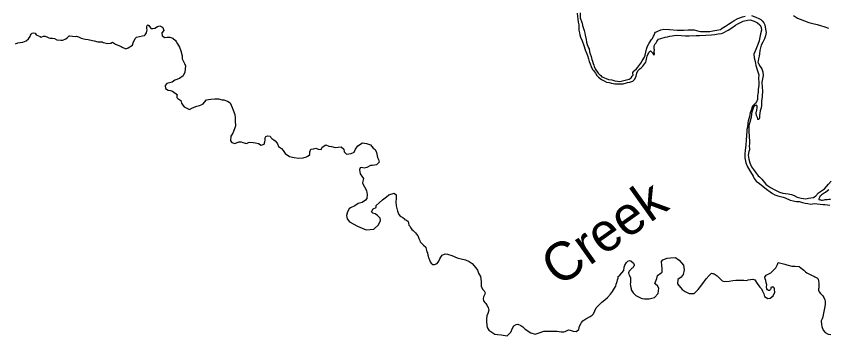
# Model space of a CAD drawing. Extents: x 79818 to 83933, y 50884 to 53307.
# Drawn here: x 81014.4 to 81163.3, y 52935.5 to 52994.1 of the extents above; entities that cross this region are included whole.
import ezdxf

# ---------------------------------------------------------------- set-up
doc = ezdxf.new("R2010")
doc.units = 0
for name, color, linetype in [('Level 10', 7, 'Continuous'), ('Level 2', 7, 'Continuous'), ('Level 9', 7, 'Continuous')]:
    doc.layers.add(name, color=color, linetype=linetype)

msp = doc.modelspace()

# ---------------------------------------------------------------- linework, layer by layer
at = {"layer": 'Level 10'}
msp.add_lwpolyline([(81156.86, 52994.25), (81157.61, 52993.8), (81158.1, 52993.59), (81158.86, 52993.27), (81159.65, 52993), (81160.42, 52992.79), (81161.19, 52992.6), (81161.8, 52992.44), (81162.57, 52992.17), (81163.25, 52991.91)], dxfattribs=at)
at = {"layer": 'Level 2'}
for points in [[(81028.39, 52989.68), (81028.7, 52989.64), (81029.37, 52989.42), (81030.14, 52989.44), (81030.35, 52989.32), (81030.66, 52989.24), (81031.14, 52989.11), (81031.71, 52989.18), (81032.05, 52989.34), (81032.62, 52989.02), (81033.64, 52988.55), (81033.82, 52988.43), (81034.49, 52988.17), (81034.94, 52988.33), (81035.69, 52988.8), (81035.81, 52989.27), (81036.19, 52990.05), (81036.43, 52990.31), (81037.02, 52990.4), (81037.53, 52990.51), (81037.91, 52990.59), (81038.05, 52990.71), (81038.27, 52991.09), (81038.36, 52991.37), (81038.38, 52991.64), (81038.36, 52991.85), (81038.36, 52992.2), (81038.37, 52992.42), (81038.49, 52992.53), (81038.72, 52992.41), (81039, 52992), (81039.18, 52991.86), (81039.44, 52991.85), (81039.78, 52991.91), (81040.26, 52992.24), (81040.71, 52992.36), (81041.07, 52992.19), (81041.27, 52992.04), (81041.47, 52991.52), (81041.1, 52991.09), (81041.15, 52990.51), (81041.62, 52990.24), (81042.05, 52990.29), (81042.58, 52990.3), (81043.1, 52990.1), (81043.56, 52989.7), (81043.73, 52989.47), (81043.93, 52989.08), (81044.33, 52988.47), (81044.57, 52987.79), (81044.8, 52986.84), (81044.84, 52986.33), (81045.26, 52985.47), (81045.42, 52985.02), (81045.32, 52983.89), (81045.01, 52983.19), (81044.32, 52982.68), (81043.45, 52982.38), (81042.95, 52982.01), (81042.51, 52981.89), (81042.01, 52981.8), (81041.71, 52981.41), (81041.74, 52980.84), (81042.22, 52980.57), (81042.67, 52980.49), (81043.03, 52980.38), (81043.94, 52979.72), (81043.85, 52979.57), (81043.85, 52979.22), (81043.99, 52979.01), (81044.57, 52978.66), (81044.68, 52978.17), (81044.96, 52977.8), (81045.16, 52977.53), (81046.17, 52977.01), (81046.71, 52977.32), (81047.52, 52977.63), (81047.99, 52977.74), (81048.61, 52977.97), (81049.24, 52978.81), (81049.66, 52978.84), (81050.05, 52978.92), (81050.77, 52978.96), (81051.45, 52978.97), (81052.14, 52978.76), (81052.42, 52978.79), (81053.13, 52978.52), (81053.63, 52978.26), (81053.97, 52977.4), (81054.16, 52976.86), (81054.46, 52976.09), (81054.5, 52975.51), (81054.53, 52974.99), (81054.57, 52973.98), (81054.12, 52972.65), (81053.73, 52972.1), (81053.68, 52971.28), (81053.9, 52970.94), (81054.48, 52970.76), (81055.19, 52971.06), (81055.63, 52971.09)], [(81014.29, 52989.06), (81014.68, 52989.22), (81015.11, 52989.33), (81015.6, 52989.39), (81016.24, 52989.6), (81016.65, 52990), (81016.95, 52990.41), (81017.01, 52990.63), (81017.14, 52990.84), (81017.3, 52990.99), (81017.62, 52991.07), (81017.86, 52991), (81018.08, 52990.72), (81018.2, 52990.67), (81018.49, 52990.5), (81018.77, 52990.39), (81018.95, 52990.31), (81019.09, 52990.35), (81019.41, 52990.47), (81019.68, 52990.48), (81020.16, 52990.27), (81020.37, 52990.15), (81020.64, 52990.09), (81021.03, 52990.09), (81021.44, 52990.02), (81021.83, 52989.82), (81022.55, 52989.72), (81022.92, 52989.76), (81023.5, 52989.96), (81023.79, 52990.23), (81024.08, 52990.51), (81024.23, 52990.52), (81024.71, 52990.44), (81025.2, 52990.39), (81025.44, 52990.44), (81025.79, 52990.35), (81026.3, 52990.13), (81027.04, 52989.89), (81027.56, 52989.83), (81028.39, 52989.68)], [(81055.63, 52971.09), (81055.94, 52970.96), (81056.6, 52970.76), (81056.98, 52970.96), (81057.24, 52971.01), (81057.82, 52970.96), (81058.22, 52970.91), (81058.83, 52970.79), (81059.27, 52970.49), (81059.65, 52970.56), (81059.82, 52970.67), (81059.99, 52971.07), (81060, 52971.45), (81060.02, 52971.82), (81060.16, 52972.03), (81060.42, 52972.15), (81060.91, 52972.13), (81061.08, 52971.9), (81061.27, 52971.7), (81061.6, 52971.44), (81061.83, 52971.24), (81062.17, 52970.88), (81062.29, 52970.7), (81062.46, 52970.25), (81063.04, 52969.88), (81063.32, 52969.48), (81063.66, 52968.96), (81064.47, 52968.38), (81065.36, 52968.22), (81066.11, 52968.11), (81067, 52968.13), (81067.57, 52968.31), (81067.87, 52968.42), (81068.23, 52968.75), (81068.23, 52969.23), (81068.42, 52969.71), (81068.9, 52969.82), (81069.33, 52969.89), (81069.74, 52969.74), (81070.28, 52969.7), (81070.45, 52970.11), (81071.17, 52970.51), (81071.68, 52970.3), (81072.2, 52970.23), (81072.85, 52970.06), (81073.38, 52970.11), (81073.94, 52970.15), (81074.45, 52969.74), (81074.49, 52969.22), (81074.91, 52968.83), (81075.35, 52968.9), (81075.78, 52968.94), (81076.31, 52969.17), (81076.59, 52969.72), (81077.03, 52970.36), (81077.84, 52970.87), (81078.6, 52970.8), (81079.33, 52970.55), (81079.83, 52969.94), (81080.2, 52969.65), (81080.4, 52969.15), (81080.62, 52968.22), (81080.77, 52967.82), (81080.89, 52967.36), (81080.41, 52966.83), (81079.71, 52966.71), (81079.3, 52966.71), (81078.64, 52966.38), (81078.18, 52966.25), (81077.65, 52966.37), (81077.45, 52966.29), (81077.32, 52965.91), (81077.44, 52965.22), (81077.83, 52964.6), (81078.05, 52964.34), (81077.93, 52963.86), (81077.84, 52963.47), (81078.24, 52962.79), (81078.62, 52962.15), (81078.69, 52961.41), (81078.65, 52960.68), (81078.38, 52960.38), (81077.77, 52959.92), (81077.06, 52959.75), (81076.45, 52959.35), (81075.65, 52958.95), (81075.42, 52958.78), (81075.11, 52958.23), (81074.92, 52957.56), (81075.02, 52956.97), (81075.5, 52956.38), (81076.95, 52955.63), (81078.23, 52955.08), (81078.62, 52954.9), (81079.94, 52955.06), (81080.81, 52955.82), (81081.17, 52956.62), (81081.07, 52957.08), (81080.63, 52957.58), (81080.18, 52957.86), (81079.77, 52957.97)], [(81079.77, 52957.97), (81079.53, 52958.22), (81079.8, 52958.78), (81080.35, 52959), (81080.37, 52959.39), (81080.94, 52959.9), (81081.54, 52960.41), (81082.26, 52961.01), (81082.71, 52961.37), (81083.65, 52961.63), (81084.04, 52961.33), (81084.04, 52960.65), (81083.94, 52960.08), (81084, 52959.34), (81084.16, 52958.83), (81084.3, 52958.37), (81084.54, 52957.77), (81084.78, 52957.46), (81085.23, 52957.18), (81085.53, 52956.93), (81085.57, 52956.81)], [(81085.57, 52956.81), (81085.95, 52956.69), (81086.2, 52956.43), (81086.28, 52956.16), (81086.37, 52955.81), (81086.53, 52955.59), (81086.75, 52955.17), (81086.91, 52954.98), (81087.14, 52954.81), (81087.59, 52954.4), (81087.96, 52953.92), (81087.99, 52953.88), (81088.2, 52953.36), (81088.35, 52952.95), (81088.45, 52952.71), (81088.67, 52952.5), (81089.04, 52952.11), (81089.44, 52951.72), (81089.55, 52951.4), (81089.68, 52950.91), (81089.76, 52950.74), (81089.81, 52950.26), (81090, 52949.69), (81090.12, 52949.45), (81090.24, 52949.08), (81090.44, 52948.82), (81090.78, 52948.59), (81091.08, 52948.58), (81091.52, 52948.76), (81091.86, 52949.16), (81092.01, 52949.59), (81092.22, 52949.9), (81092.43, 52950.3), (81093.04, 52950.51), (81093.44, 52950.48), (81094.24, 52950.19), (81095.23, 52949.77), (81095.96, 52949.62), (81096.72, 52949.41), (81097.4, 52949.11), (81097.95, 52948.77), (81098.62, 52947.95), (81098.95, 52947.55), (81099.12, 52946.97), (81099.51, 52946.34), (81099.58, 52945.47), (81099.61, 52945.04), (81099.62, 52944.53), (81099.89, 52943.97), (81100.16, 52943.74), (81100.33, 52943.38), (81100.28, 52943.15), (81100.17, 52942.86), (81100.06, 52942.66), (81099.98, 52942.24), (81100.05, 52941.88), (81100.31, 52941.59), (81100.44, 52941.4), (81100.64, 52941.12), (81100.9, 52940.67), (81101.03, 52940.19), (81100.8, 52939.58), (81100.66, 52939.12), (81100.57, 52938.61), (81100.56, 52938.12), (81100.65, 52937.42), (81100.73, 52937.01), (81101.01, 52936.54), (81101.54, 52936.15), (81102.14, 52935.81), (81102.63, 52935.71), (81103.3, 52935.67), (81104.36, 52935.49), (81105.06, 52936.18), (81105.37, 52936.88), (81105.62, 52937.3), (81106, 52937.57), (81106.32, 52937.6), (81106.87, 52937.39), (81107.24, 52937.12), (81107.68, 52936.72), (81108.74, 52936.02), (81109.49, 52935.81), (81110.23, 52936.06), (81111.11, 52936.33), (81111.91, 52936.36), (81112.58, 52936.33), (81113.19, 52936.32), (81113.55, 52936.34), (81114.24, 52936.24), (81114.48, 52936.19), (81114.74, 52936.24), (81115.01, 52936.28), (81115.61, 52936.57), (81115.93, 52936.52), (81116.48, 52936.33), (81117.03, 52936.3), (81117.48, 52936.64), (81117.66, 52937.24), (81117.87, 52937.67), (81118.01, 52937.91)], [(81118.01, 52937.91), (81118.24, 52938.25), (81118.4, 52938.35), (81118.78, 52938.59), (81119.58, 52939.01), (81119.93, 52939.25), (81120.18, 52939.53), (81120.43, 52940.07), (81120.69, 52940.6), (81121.29, 52941.21), (81121.73, 52941.63), (81122.3, 52942.09), (81122.76, 52942.49), (81123.32, 52943.14), (81123.68, 52943.62), (81124.05, 52944.21), (81124.26, 52944.61), (81124.36, 52944.93), (81124.56, 52945.44), (81124.58, 52945.75), (81124.69, 52946.08), (81124.73, 52946.36), (81125, 52946.59), (81125.39, 52947.01), (81125.73, 52947.48), (81125.83, 52948.1), (81125.96, 52948.47), (81126.22, 52948.94), (81126.22, 52948.95), (81126.49, 52949.19), (81126.81, 52949.31), (81127.06, 52949.24), (81127.53, 52948.81), (81127.6, 52948.66), (81127.62, 52948.56), (81127.63, 52948.35), (81127.53, 52948.19), (81127.38, 52947.98), (81127.19, 52947.84), (81127.07, 52947.73), (81126.76, 52947.37), (81126.7, 52947.2), (81126.64, 52947.02), (81126.69, 52946.79), (81126.81, 52946.58), (81126.98, 52946.14), (81127, 52945.71), (81126.99, 52945.63), (81126.99, 52945.15), (81126.94, 52945), (81126.98, 52944.66), (81127.01, 52944.36), (81127.09, 52944.17), (81127.12, 52943.89), (81127.45, 52943.38), (81127.97, 52942.91), (81128.21, 52942.75), (81128.35, 52942.68), (81128.94, 52942.37), (81129.14, 52942.3), (81129.53, 52942.27), (81129.72, 52942.26), (81130.37, 52942.29), (81131.39, 52942.5), (81132.04, 52943.27), (81132.16, 52944.24), (81131.93, 52944.64), (81131.58, 52944.95), (81131.43, 52945.08), (81131.69, 52945.7), (81131.83, 52945.99), (81131.91, 52946.57), (81132.62, 52947.05), (81132.8, 52947.19), (81132.75, 52947.85), (81132.72, 52948.36), (81132.68, 52949.09), (81132.89, 52949.43), (81133.68, 52949.76), (81134.28, 52949.79), (81135.21, 52949.84), (81135.88, 52949.34), (81136.67, 52948.44), (81136.83, 52947.57), (81136.62, 52946.76), (81136.27, 52946.26), (81135.66, 52945.79), (81135.59, 52945.02), (81136.44, 52944), (81136.98, 52943.6), (81137.72, 52943.26), (81138.65, 52943.27), (81139.4, 52943.97), (81140.08, 52944.84), (81140.83, 52945.93), (81141.38, 52946.56), (81141.85, 52946.95), (81142, 52946.93), (81142.12, 52946.94), (81142.34, 52946.88), (81142.89, 52946.5)], [(81142.89, 52946.5), (81143.32, 52946), (81143.8, 52945.6), (81144.25, 52945.42), (81145.08, 52945.5), (81145.72, 52945.61), (81146.26, 52945.71), (81146.79, 52945.72), (81147.14, 52945.7), (81147.74, 52945.67), (81148.25, 52945.64), (81148.57, 52945.73), (81148.94, 52945.84), (81149.42, 52945.88), (81149.78, 52945.78), (81150.17, 52945.07), (81150.47, 52944.65), (81150.71, 52944.41), (81151, 52944.08), (81151.19, 52943.67), (81151.4, 52943.16), (81151.54, 52942.71), (81152.17, 52942.3), (81152.55, 52942.37), (81153.13, 52942.85), (81153.43, 52943.49), (81153.39, 52943.97), (81153.38, 52944.1), (81153.33, 52944.31), (81153.16, 52944.41), (81153.09, 52944.44), (81152.92, 52944.47), (81152.85, 52944.44), (81152.69, 52944.35), (81152.67, 52944.13), (81152.66, 52944), (81152.54, 52943.83), (81152.44, 52943.79), (81152.43, 52943.79), (81152.28, 52943.78), (81152.26, 52943.8), (81152.07, 52943.95), (81151.96, 52944.13), (81151.9, 52944.45), (81151.94, 52944.82), (81151.85, 52945.2), (81151.77, 52945.61), (81151.68, 52945.92), (81151.6, 52946.24), (81151.82, 52946.64), (81152.69, 52947.07), (81153.22, 52947.56), (81153.62, 52947.93), (81153.93, 52948.56), (81154.03, 52948.92), (81155.28, 52948.6), (81155.6, 52948.52), (81156.56, 52948.25), (81157.15, 52948.26), (81157.91, 52948.23), (81158.22, 52947.93), (81158.48, 52947.71), (81158.73, 52947.5), (81159.04, 52947.22), (81159.28, 52947.05), (81159.65, 52946.83), (81159.88, 52946.71), (81160.28, 52946.55), (81160.58, 52946.41), (81160.78, 52946.3), (81161.24, 52946.07), (81161.28, 52945.97), (81161.38, 52945.8), (81161.42, 52945.68), (81161.45, 52945.48), (81161.5, 52945.19), (81161.5, 52944.91), (81161.49, 52944.29), (81161.46, 52944.13), (81161.46, 52943.85), (81161.55, 52943.58), (81161.77, 52943.26), (81162.02, 52943), (81162.2, 52942.8), (81162.43, 52942.49), (81162.57, 52942.06), (81162.64, 52941.86), (81162.66, 52941.32), (81162.59, 52940.89), (81162.5, 52940.27), (81162.34, 52939.62), (81162.23, 52938.99), (81162.08, 52938.57), (81161.95, 52938.24), (81162, 52937.57), (81162.02, 52937.18), (81162.3, 52936.51), (81162.68, 52936.12), (81163.23, 52935.8), (81163.71, 52935.7)]]:
    msp.add_lwpolyline(points, dxfattribs=at)
at = {"layer": 'Level 9'}
for points in [[(81117.21, 52994.68), (81117.28, 52994.08), (81117.34, 52993.59), (81117.4, 52993.04), (81117.48, 52992.56), (81117.53, 52992.07), (81117.53, 52991.57), (81117.63, 52991.1), (81117.71, 52990.7), (81117.81, 52990.3), (81118.09, 52989.58), (81118.42, 52988.77), (81118.65, 52987.93), (81118.98, 52987.24), (81119.11, 52986.92), (81119.28, 52986.33), (81119.4, 52985.82), (81119.6, 52985.37), (81119.74, 52984.88), (81120.01, 52984.37), (81120.18, 52984.17), (81120.55, 52983.68), (81120.8, 52983.22), (81121.13, 52982.92), (81121.69, 52982.49), (81122.14, 52982.25), (81122.56, 52982.05), (81123.05, 52981.96), (81123.52, 52981.84), (81124.09, 52981.73), (81124.84, 52981.73), (81125.64, 52981.75), (81126.42, 52981.96), (81126.86, 52982.03), (81127.39, 52982.21), (81127.78, 52982.6), (81128, 52983.1), (81128.15, 52983.68), (81128.34, 52984.12), (81128.71, 52984.5), (81129, 52984.72), (81129.23, 52984.98), (81129.58, 52985.44), (81129.8, 52985.72), (81129.85, 52985.97), (81129.97, 52986.53), (81130.06, 52986.81), (81130.14, 52987.08), (81130.27, 52987.31), (81130.38, 52987.52), (81130.46, 52987.64), (81130.66, 52987.76), (81130.89, 52987.56), (81130.92, 52987.45), (81131, 52987.38), (81131.17, 52987.1), (81131.23, 52987.06), (81131.38, 52987.1), (81131.4, 52987.25), (81131.34, 52987.65), (81131.37, 52987.93), (81131.29, 52988.16), (81131.3, 52988.37), (81131.31, 52988.51), (81131.34, 52988.72), (81131.51, 52989.05)], [(81117.73, 52994.74), (81117.77, 52993.86), (81118.04, 52992.95), (81118.11, 52992.84), (81118.21, 52992.43), (81118.48, 52991.51), (81118.61, 52991.03), (81118.67, 52990.67), (81118.84, 52989.85), (81118.93, 52989.37), (81119.03, 52988.93), (81119.3, 52988.33), (81119.38, 52988.12), (81119.47, 52987.62), (81119.58, 52987.2), (81119.74, 52986.73), (81119.9, 52986.21), (81120.04, 52985.85), (81120.16, 52985.46), (81120.27, 52985.12), (81120.34, 52984.89), (81120.51, 52984.47), (81120.62, 52984.26), (81120.9, 52983.89), (81121.04, 52983.67), (81121.24, 52983.5), (81121.51, 52983.26), (81121.75, 52983.01), (81121.89, 52982.93), (81122.51, 52982.68), (81122.93, 52982.53), (81123.56, 52982.43), (81124.11, 52982.29), (81124.59, 52982.18), (81124.94, 52982.17), (81125.24, 52982.18), (81126.27, 52982.43), (81126.72, 52982.59), (81127.09, 52982.84), (81127.31, 52983.12), (81127.44, 52983.32), (81127.47, 52983.39), (81127.43, 52983.49), (81127.4, 52983.63), (81127.43, 52983.82), (81127.57, 52984.03), (81127.69, 52984.16), (81128.05, 52984.45), (81128.32, 52984.77), (81128.68, 52985.29), (81128.87, 52985.53), (81129.14, 52985.93), (81129.57, 52986.6), (81129.66, 52986.98), (81129.78, 52987.51), (81129.89, 52988.1), (81130.09, 52988.65), (81130.42, 52989.19), (81130.84, 52989.87), (81131.01, 52990.06), (81131.22, 52990.46), (81131.32, 52990.65), (81131.46, 52991.03), (81131.53, 52991.18), (81131.73, 52991.29), (81131.98, 52991.37), (81132.56, 52991.63), (81133.09, 52991.75), (81134.15, 52991.66), (81135.5, 52991.56), (81135.54, 52991.56), (81136.05, 52991.59), (81136.66, 52991.58), (81137.56, 52991.62), (81137.88, 52991.63), (81138.62, 52991.6), (81139.49, 52991.4), (81139.81, 52991.35), (81140.33, 52991.34), (81141.09, 52991.32), (81141.54, 52991.35), (81142.08, 52991.45), (81142.77, 52991.59), (81143.45, 52991.72), (81143.78, 52991.91), (81144.36, 52992.29), (81144.94, 52992.68), (81145.6, 52993.12), (81146, 52993.34), (81146.67, 52993.73), (81147.49, 52994.02), (81147.98, 52994.14)], [(81131.51, 52989.05), (81131.65, 52989.25), (81131.8, 52989.47), (81131.95, 52989.68), (81132.12, 52989.93), (81132.54, 52990.04), (81133.3, 52990.26), (81133.78, 52990.33), (81134.21, 52990.45), (81135.4, 52990.67), (81136.29, 52990.58), (81137.03, 52990.55), (81137.71, 52990.51), (81139.02, 52990.58), (81139.65, 52990.61), (81140.78, 52990.68), (81141.8, 52990.7), (81142.43, 52990.78), (81143.02, 52990.88), (81143.63, 52990.97), (81143.98, 52991.08), (81144.86, 52991.56), (81145.55, 52991.98), (81146.23, 52992.46), (81146.65, 52992.71), (81147.25, 52993.03), (81147.61, 52993.22), (81148.43, 52993.43), (81148.91, 52993.45), (81149.67, 52993.22), (81150.23, 52992.93), (81150.66, 52992.54), (81150.92, 52992.1), (81150.96, 52991.59), (81150.79, 52990.88), (81150.65, 52990.26), (81150.53, 52989.63), (81150.34, 52988.93), (81149.96, 52988.04), (81149.57, 52987.16), (81149.66, 52986.47), (81149.83, 52985.84), (81149.94, 52985.07), (81150.32, 52983.9), (81150.48, 52983.35), (81150.43, 52982.76), (81150.47, 52981.92), (81150.49, 52981.41), (81150.39, 52980.76), (81150.38, 52980.22), (81150.32, 52979.87), (81150.28, 52979.49), (81150.23, 52978.82), (81150.06, 52978.44), (81149.9, 52978.19), (81149.75, 52978.04), (81149.57, 52977.88), (81149.4, 52977.68), (81149.24, 52977.35), (81149.15, 52977.04), (81149.11, 52976.88), (81148.92, 52976.39), (81148.87, 52976.07), (81148.8, 52975.72), (81148.68, 52975.31), (81148.55, 52974.89), (81148.5, 52974.62), (81148.47, 52974.34), (81148.43, 52973.89), (81148.41, 52973.78), (81148.32, 52973.33), (81148.29, 52972.95), (81148.22, 52972.32), (81148.2, 52971.36), (81148.11, 52970.52), (81148.05, 52969.96), (81148, 52969.52), (81147.95, 52968.79), (81147.92, 52968.16), (81148.12, 52967.25), (81148.42, 52966.5), (81148.96, 52965.58), (81149.48, 52964.77), (81149.62, 52964.36), (81149.99, 52963.85), (81150.59, 52963.45), (81151.88, 52962.42), (81152.55, 52961.88), (81153, 52961.58), (81153.4, 52961.33), (81153.98, 52961.18), (81154.93, 52960.94), (81155.34, 52960.79), (81156.26, 52960.36), (81156.77, 52960.23), (81157.37, 52960.13), (81157.89, 52960.13), (81158.48, 52959.94), (81159.01, 52959.8), (81159.47, 52959.74), (81160.05, 52959.67)], [(81149.18, 52994.28), (81149.94, 52993.98), (81150.49, 52993.72), (81150.85, 52993.51), (81151.12, 52993.3), (81151.42, 52992.94), (81151.59, 52992.54)], [(81151.59, 52992.54), (81151.69, 52991.78), (81151.81, 52991.17), (81151.7, 52990.52), (81151.54, 52990), (81151.21, 52989.37), (81150.93, 52988.8), (81150.68, 52987.86), (81150.6, 52987.25), (81150.54, 52986.8), (81150.43, 52986.32), (81150.35, 52985.96), (81150.33, 52985.72), (81150.42, 52985.45), (81150.74, 52984.92), (81151.06, 52984.49), (81151.24, 52983.95), (81151.28, 52983.24), (81151.15, 52982.63), (81151.02, 52982.02), (81151.12, 52981.07), (81151.15, 52980.41), (81151.08, 52979.39), (81151.01, 52978.52), (81150.98, 52977.76), (81150.91, 52977.29), (81150.77, 52976.75), (81150.67, 52976.35), (81150.63, 52975.93), (81150.63, 52975.6), (81150.59, 52975.43), (81150.53, 52975.35), (81150.48, 52975.18), (81150.32, 52975.18), (81150.32, 52975.27), (81150.25, 52975.54), (81150.19, 52975.66), (81150.08, 52975.9), (81150.04, 52976.04), (81150.03, 52976.13), (81150.03, 52976.38), (81150.06, 52976.7), (81150.1, 52976.81), (81150.13, 52977.04), (81150.18, 52977.27), (81150.2, 52977.57), (81150.16, 52977.72), (81150.03, 52977.8), (81149.84, 52977.75), (81149.61, 52977.54), (81149.44, 52977.27), (81149.23, 52976.51), (81149.18, 52976.19), (81149.08, 52975.52), (81148.97, 52975.16), (81148.89, 52974.9), (81148.78, 52974.53), (81148.71, 52974.3), (81148.67, 52973.95), (81148.64, 52973.62), (81148.65, 52973.41), (81148.64, 52973.22), (81148.67, 52972.79), (81148.71, 52972.23), (81148.73, 52971.96), (81148.81, 52971.24), (81148.78, 52970.76), (81148.72, 52970.27), (81148.8, 52969.79), (81148.81, 52969.62), (81148.69, 52969.3), (81148.57, 52968.62), (81148.66, 52967.91), (81148.82, 52967.21), (81149.13, 52966.46), (81149.51, 52966), (81150, 52965.3), (81150.36, 52964.86), (81150.59, 52964.66), (81151.05, 52964.2), (81151.75, 52963.33), (81152.07, 52963.07), (81152.62, 52962.72), (81153.44, 52962.29), (81154.27, 52961.86), (81154.88, 52961.68), (81155.88, 52961.53), (81156.46, 52961.42), (81156.95, 52961.21), (81157.55, 52960.93), (81158.27, 52960.73), (81159.11, 52960.6), (81159.61, 52960.76), (81160.05, 52960.78), (81160.52, 52960.86), (81160.92, 52961.15), (81161.46, 52961.71), (81161.99, 52962.06), (81162.52, 52962.46), (81162.87, 52962.87), (81163.24, 52963.32)], [(81163.24, 52963.32), (81163.73, 52963.84)], [(81163.65, 52960.47), (81163.31, 52960.47), (81163, 52960.46), (81162.62, 52960.42), (81162.38, 52960.37), (81162.18, 52960.33), (81162.02, 52960.32), (81161.76, 52960.41), (81161.68, 52960.4), (81161.56, 52960.43), (81161.54, 52960.47), (81161.56, 52960.63), (81161.58, 52960.71), (81161.65, 52960.9), (81161.8, 52961.22), (81162, 52961.35), (81162.12, 52961.46), (81162.49, 52961.71), (81162.71, 52961.87), (81163.1, 52962.16), (81163.32, 52962.36)], [(81160.05, 52959.67), (81160.63, 52959.74), (81161.2, 52959.68), (81161.76, 52959.62), (81162.3, 52959.6), (81162.61, 52959.55), (81163.07, 52959.5), (81163.49, 52959.48)]]:
    msp.add_lwpolyline(points, dxfattribs=at)

# ---------------------------------------------------------------- texts
msp.add_text('Creek', height=7.04, rotation=35.3625, dxfattribs=at).set_placement((81113.87, 52944.32))

doc.saveas('drawing.dxf')
